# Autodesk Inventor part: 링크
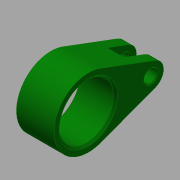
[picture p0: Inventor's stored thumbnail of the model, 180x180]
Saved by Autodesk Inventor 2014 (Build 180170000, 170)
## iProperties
Created: 2016-08
Part Number: 링크
Material: 강철, 탄소
Document SubType Name: Modeling
Designer: mduedu
Density: 7.87 g/cm^3
Appearance: 진녹색
Author: mduedu
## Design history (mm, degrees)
sketch "스케치1"
  geometry: L1 (32.1, 5.62)-(5.775, 15.456); L2 (32.1, -5.62)-(5.775, -15.456); C1 r 13 at (0, 0); C2 r 3 at (30, 0); A1 r 16.5 centre (0, 0) between (5.775, 15.456) and (5.775, -15.456); A2 r 6 centre (30, 0) between (32.1, 5.62) and (32.1, -5.62); 1 further point
  constraints: 4 centre point, 4 end point, 4 point on circle, 4 tangent, 3 coincident, 1 horizontal alignment
  dimensions: "d0" = 33 diameter of A1; "d2" = 12 diameter of A2; "d3" = 30 distance of A2.centre point (0, 0); "d4" = 26 diameter of C1; "d5" = 6 diameter of C2
extrude "돌출1" new body sketch "스케치1" stored distance "d6" = 18; taper "d7" = 0 deg
sketch "스케치2"
  geometry: L1 (-9, 36)-(9, 36) reference; L2 (0, 0)-(0, 36); L3 (-4, 36)-(4, 36); L4 (4, 36)-(4, 22); L5 (4, 22)-(-4, 22); L6 (-4, 22)-(-4, 36)
  constraints: 10 end point, 2 midpoint, 2 parallel, 1 horizontal, 1 perpendicular, 1 point on line
  dimensions: "d8" = 8 distance between parallel lines of L4 L6; "d10" = 14 distance of L3.end L4.end
extrude "돌출2" cut sketch "스케치2" stored distance "d11" = 20; taper "d12" = 0 deg
chamfer "모따기1" distance "d13" = 1; stored, may be unused: second distance "d14" = 2, angle "d15" = 45 deg
chamfer "모따기2" distance "d16" = 0.5; stored, may be unused: second distance "d17" = 2, angle "d18" = 45 deg
node "솔리드1"
